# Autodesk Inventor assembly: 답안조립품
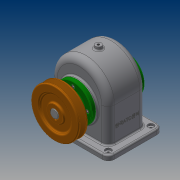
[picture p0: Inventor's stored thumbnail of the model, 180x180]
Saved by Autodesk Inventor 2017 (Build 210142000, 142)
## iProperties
Part Number: 답안조립품
Material: 일반
Document SubType Name: Assembly
Designer: 20
Author: 20
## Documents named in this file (13)
- C:\Users\20\Desktop\480310V1002\답안조립품.iam
- C:\Users\20\Desktop\480310V1002\본체.ipt
- C:\Users\20\Desktop\480310V1002\앞커버.ipt
- C:\Users\20\Desktop\480310V1002\뒤커버.ipt
- C:\Users\20\Desktop\480310V1002\볼트 M4.ipt
- C:\Users\20\Desktop\480310V1002\베어링 6203.ipt
- C:\Users\20\Desktop\480310V1002\축.ipt
- C:\Users\20\Desktop\480310V1002\스퍼기어.ipt
- C:\Users\20\Desktop\480310V1002\키 6x6x22.ipt
- C:\Users\20\Desktop\480310V1002\부시.ipt
- C:\Users\20\Desktop\480310V1002\V-벨트풀리.ipt
- C:\Users\20\Desktop\480310V1002\멈춤나사 M4.ipt
- C:\Users\20\Desktop\480310V1002\키 5x5x18.ipt
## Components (1 placed, 1 different names)
1. V-벨트풀리:1 — 플러쉬:2
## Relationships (1: Flush 1)
- 플러쉬:2 [Flush]: V-벨트풀리:1
